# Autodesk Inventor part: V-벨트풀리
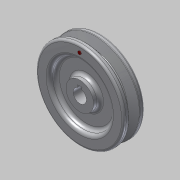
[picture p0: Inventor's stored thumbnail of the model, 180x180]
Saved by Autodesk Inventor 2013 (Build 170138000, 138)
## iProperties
Created: 2016-08
Part Number: V-벨트풀리
Material: 알루미늄 6061
Document SubType Name: Modeling
Designer: mduedu
Density: 2.71 g/cm^3
Author: mduedu
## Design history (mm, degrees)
sketch "스케치1"
  geometry: L1 (0, 9.5)-(0, -9.5); L2 (0, 9.5)-(40, 9.5); L3 (40, 9.5)-(40, 4.877); L4 (40, 4.877)-(31, 1.953); L5 (31, 1.953)-(31, 0); L6 (0, 0)-(31, 0); L7 (0, -9.5)-(40, -9.5); L8 (40, -9.5)-(40, -4.877); L9 (40, -4.877)-(31, -1.953); L10 (31, -1.953)-(31, 0); L11 (37.3, 9.5)-(37.3, -9.5); 3 further points
  constraints: 22 end point, 6 point on line, 4 perpendicular, 3 symmetric about line, 1 coincident, 1 horizontal alignment, 1 midpoint, 1 parallel, 1 vertical
  dimensions: "d0" = 19 distance of L1.start L1.end; "d2" = 80 diameter of L8 L1; "d4" = 6.3 distance between parallel lines of L10 L11; "d5" = 2.7 distance between parallel lines of L11 L8; "d6" = 8 distance of point (37.3, -4) point (37.3, 4); "d7" = 36 deg angle of L9 L4
revolve "회전1" sketch "스케치1" stored, may be unused: angle "d8" = 90 deg
sketch "스케치2"
  geometry: L1 (-2, 0)-(2, 0); L2 (2, 0)-(2, 7.8); L3 (2, 7.8)-(-2, 7.8); L4 (-2, 7.8)-(-2, 0); C1 r 6 at (0, 0); 2 further points
  constraints: 8 end point, 2 coincident, 2 parallel, 1 centre point, 1 horizontal, 1 midpoint, 1 perpendicular
  dimensions: "d9" = 12 diameter of C1; "d11" = 4 distance of L2.end L3.end; "d12" = 7.8 distance of L1.end L2.end
extrude "돌출1" cut sketch "스케치2" stored distance "d13" = 10; taper "d14" = 0 deg
sketch "스케치4"
  geometry: C1 r 27.5 at (0, 0); C2 r 12.5 at (0, 0); 1 further point
  constraints: 2 centre point, 2 coincident
  dimensions: "d30" = 55 diameter of C1; "d31" = 25 diameter of C2
extrude "돌출2" cut sketch "스케치4" distance "d32" = 6; taper "d33" = 0 deg
fillet "모깎기6" dims "d34" = 3
fillet "모깎기7" dims "d35" = 0.5, "d36" = 1, "d37" = 2
chamfer "모따기1" distance "d26" = 0.5; stored, may be unused: second distance "d27" = 2, angle "d28" = 45 deg
sketch "스케치5" dims "d38" = 68
  geometry: C1 r 1.5 at (0, 34); 2 further points
  constraints: 2 vertical alignment, 1 centre point, 1 coincident, 2 other
  dimensions: "d40" = 3 diameter of C1
extrude "돌출3" join sketch "스케치5" distance "d41" = 0.5; taper "d42" = 0 deg
node "솔리드1"
mirror "대칭2"
